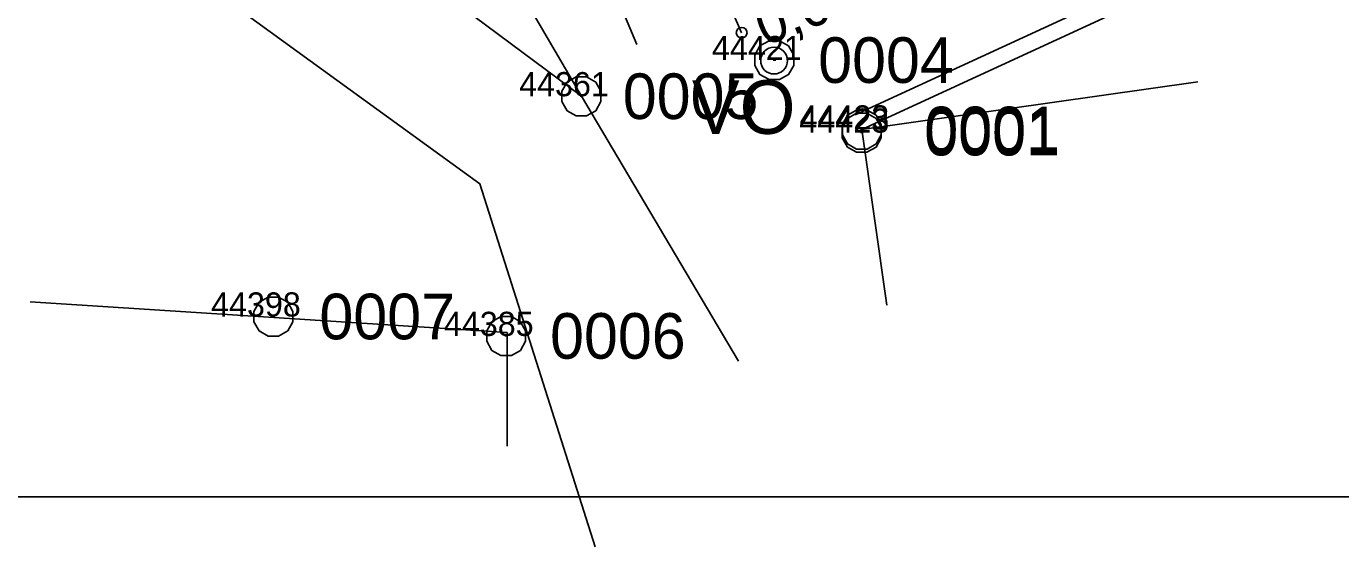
# Model space of a CAD drawing. Extents: x -598521 to -597689, y -1074676 to -1074150.
# Drawn here: x -598496.3 to -598471.79, y -1074225.1 to -1074215.4 of the extents above; entities that cross this region are included whole.
import ezdxf

# ---------------------------------------------------------------- set-up
doc = ezdxf.new("R2010")
doc.units = 0
for name, color, linetype in [('Vrstva 1', 7, 'Continuous'), ('Vrstva 10', 7, 'Continuous'), ('Vrstva 12', 7, 'Continuous'), ('Vrstva 2', 7, 'Continuous'), ('Vrstva 3', 7, 'Continuous'), ('Vrstva 40', 7, 'Continuous'), ('Vrstva 5', 7, 'Continuous')]:
    doc.layers.add(name, color=color, linetype=linetype)

msp = doc.modelspace()

# ---------------------------------------------------------------- linework, layer by layer
at = {"layer": 'Vrstva 1'}
for p, q in [((-598482.377, -1074216.026), (-598482.327, -1074216.026)), ((-598485.974, -1074216.7), (-598485.924, -1074216.7)), ((-598480.746, -1074217.379), (-598480.696, -1074217.379)), ((-598480.745, -1074217.32), (-598480.695, -1074217.32)), ((-598491.719, -1074220.809), (-598491.669, -1074220.809)), ((-598487.377, -1074221.171), (-598487.327, -1074221.171))]:
    msp.add_line(p, q, dxfattribs=at)
for points in [[(-598482.257, -1074215.666), (-598482.087, -1074215.761), (-598481.992, -1074215.931), (-598481.992, -1074216.126), (-598482.087, -1074216.296), (-598482.257, -1074216.391), (-598482.452, -1074216.391), (-598482.622, -1074216.296), (-598482.717, -1074216.126), (-598482.717, -1074215.931), (-598482.622, -1074215.761), (-598482.452, -1074215.666)], [(-598485.854, -1074216.34), (-598485.684, -1074216.435), (-598485.589, -1074216.605), (-598485.589, -1074216.8), (-598485.684, -1074216.97), (-598485.854, -1074217.065), (-598486.049, -1074217.065), (-598486.219, -1074216.97), (-598486.314, -1074216.8), (-598486.314, -1074216.605), (-598486.219, -1074216.435), (-598486.049, -1074216.34)], [(-598480.625, -1074216.96), (-598480.455, -1074217.055), (-598480.36, -1074217.225), (-598480.36, -1074217.42), (-598480.455, -1074217.59), (-598480.625, -1074217.685), (-598480.82, -1074217.685), (-598480.99, -1074217.59), (-598481.085, -1074217.42), (-598481.085, -1074217.225), (-598480.99, -1074217.055), (-598480.82, -1074216.96)], [(-598480.626, -1074217.019), (-598480.456, -1074217.114), (-598480.361, -1074217.284), (-598480.361, -1074217.479), (-598480.456, -1074217.649), (-598480.626, -1074217.744), (-598480.821, -1074217.744), (-598480.991, -1074217.649), (-598481.086, -1074217.479), (-598481.086, -1074217.284), (-598480.991, -1074217.114), (-598480.821, -1074217.019)], [(-598491.599, -1074220.449), (-598491.429, -1074220.544), (-598491.334, -1074220.714), (-598491.334, -1074220.909), (-598491.429, -1074221.079), (-598491.599, -1074221.174), (-598491.794, -1074221.174), (-598491.964, -1074221.079), (-598492.059, -1074220.909), (-598492.059, -1074220.714), (-598491.964, -1074220.544), (-598491.794, -1074220.449)], [(-598487.257, -1074220.811), (-598487.087, -1074220.906), (-598486.992, -1074221.076), (-598486.992, -1074221.271), (-598487.087, -1074221.441), (-598487.257, -1074221.536), (-598487.452, -1074221.536), (-598487.622, -1074221.441), (-598487.717, -1074221.271), (-598487.717, -1074221.076), (-598487.622, -1074220.906), (-598487.452, -1074220.811)]]:
    msp.add_lwpolyline(points, close=True, dxfattribs=at)
at = {"layer": 'Vrstva 10'}
for points in [[(-598484.92, -1074215.734), (-598487.958, -1074208.491), (-598488.57, -1074195.13), (-598485.971, -1074186.446), (-598483.586, -1074182.241), (-598482.242, -1074177.742), (-598479.451, -1074171.782), (-598475.091, -1074167.2), (-598468.639, -1074162.188), (-598465.635, -1074160.81), (-598454.605, -1074159.518), (-598444.717, -1074161.464), (-598440.447, -1074163.564)], [(-598491.251, -1074170.54), (-598490.39, -1074175.72), (-598490.72, -1074179.9), (-598491.56, -1074186.02), (-598491.51, -1074191.2), (-598489.94, -1074209.87), (-598485.95, -1074216.7)], [(-598483.025, -1074221.641), (-598485.95, -1074216.7), (-598492.6, -1074211.75), (-598492.675, -1074194.409), (-598492.11, -1074185.98), (-598491.774, -1074180.11), (-598492.357, -1074176.088), (-598493.045, -1074170.76)], [(-598485.692, -1074225.103), (-598487.847, -1074218.331), (-598494.92, -1074213.2), (-598495.961, -1074193.667), (-598495.219, -1074186.141), (-598494.954, -1074180.929), (-598495.873, -1074176.106), (-598499.01, -1074172.05)], [(-598480.846, -1074217.048), (-598466.668, -1074210.51), (-598452.741, -1074209.434), (-598445.724, -1074211.895)], [(-598480.72, -1074217.32), (-598466.591, -1074210.805), (-598452.781, -1074209.738), (-598445.79, -1074212.19)], [(-598474.458, -1074216.43), (-598480.72, -1074217.32), (-598480.254, -1074220.6)], [(-598487.339, -1074223.225), (-598487.339, -1074221.108), (-598496.23, -1074220.537)]]:
    msp.add_lwpolyline(points, dxfattribs=at)
msp.add_circle((-598482.358, -1074216.035), 0.25, dxfattribs=at)
at = {"layer": 'Vrstva 12'}
msp.add_spline([(-598477.856, -1074175.904), (-598479.108, -1074177.873), (-598481.873, -1074181.144), (-598482.714, -1074182.62), (-598484.125, -1074188.19), (-598485.335, -1074196.141), (-598485.114, -1074200.364), (-598484.5, -1074206.655), (-598482.536, -1074211.254), (-598480.207, -1074214.488), (-598467.793, -1074210.214), (-598459.725, -1074208.727), (-598453.744, -1074207.761), (-598434.045, -1074202.26), (-598426.944, -1074195.607), (-598420.2, -1074189.398), (-598414.755, -1074180.164), (-598419.159, -1074177.729), (-598424.716, -1074175.666), (-598432.261, -1074171.95), (-598446.273, -1074165.334), (-598449.284, -1074163.066), (-598455.078, -1074161.455), (-598458.605, -1074161.801), (-598464.281, -1074162.718), (-598468.112, -1074164.562), (-598472.279, -1074167.706), (-598475.138, -1074168.205), (-598476.252, -1074168.916), (-598476.978, -1074169.714), (-598477.609, -1074175.205), (-598477.856, -1074175.904)], degree=3, dxfattribs=at)
at = {"layer": 'Vrstva 40'}
msp.add_line((-598520.773, -1074224.17), (-598374.273, -1074224.17), dxfattribs=at)
at = {"layer": 'Vrstva 5'}
msp.add_lwpolyline([(-598482.963, -1074215.515), (-598486.401, -1074207.525), (-598486.999, -1074195.022), (-598480.548, -1074179.991), (-598475.294, -1074170.015), (-598468.112, -1074164.562), (-598464.254, -1074162.567), (-598455.078, -1074161.455), (-598445.366, -1074162.766), (-598432.996, -1074169.084), (-598417.866, -1074175.801), (-598412.373, -1074178.959)], dxfattribs=at)
msp.add_circle((-598482.963, -1074215.515), 0.1, dxfattribs=at)

# ---------------------------------------------------------------- texts
at = {"layer": 'Vrstva 10'}
msp.add_text('0,0', height=0.75, rotation=21.1697, dxfattribs=at).set_placement((-598482.533, -1074215.77))
msp.add_text('VO', height=1, dxfattribs=at).set_placement((-598483.892, -1074217.402))
at = {"layer": 'Vrstva 2'}
for s, p in [('0004', (-598481.536, -1074216.451)), ('0005', (-598485.18, -1074217.125)), ('0001', (-598479.557, -1074217.804)), ('0001', (-598479.556, -1074217.745)), ('0007', (-598490.838, -1074221.234)), ('0006', (-598486.536, -1074221.596))]:
    msp.add_text(s, height=0.85, dxfattribs=at).set_placement(p)
at = {"layer": 'Vrstva 3'}
for s, p in [('44421', (-598483.517, -1074216.026)), ('44361', (-598487.113, -1074216.7)), ('44423', (-598481.886, -1074217.379)), ('44423', (-598481.884, -1074217.32)), ('44398', (-598492.858, -1074220.809)), ('44385', (-598488.516, -1074221.171))]:
    msp.add_text(s, height=0.45, dxfattribs=at).set_placement(p)

doc.saveas('drawing.dxf')
